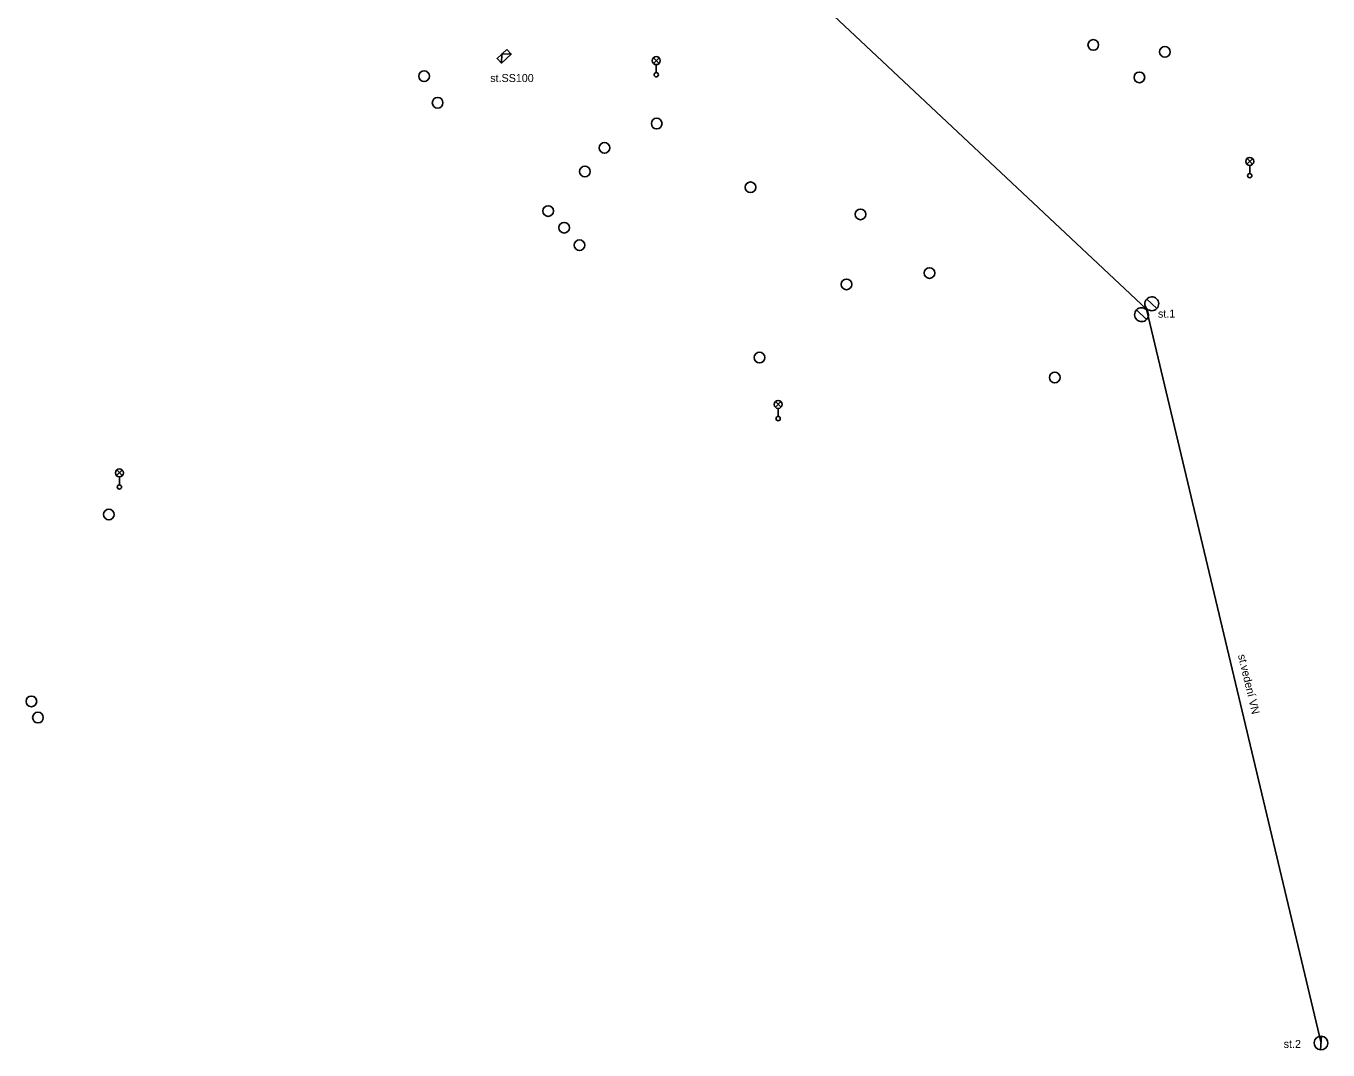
# Model space of a CAD drawing. Extents: x -762500 to -761250, y -1152983 to -1152297.
# Drawn here: x -762376.5 to -762254.5, y -1152983.3 to -1152887.3 of the extents above; entities that cross this region are included whole.
import ezdxf

# ---------------------------------------------------------------- set-up
doc = ezdxf.new("R2010")
doc.units = 0
for name, color, linetype in [('Vrstva 1', 7, 'Continuous'), ('Vrstva 2', 7, 'Continuous'), ('Vrstva 9', 7, 'Continuous')]:
    doc.layers.add(name, color=color, linetype=linetype)

msp = doc.modelspace()

# ---------------------------------------------------------------- linework, layer by layer
at = {"layer": 'Vrstva 1'}
for p, q in [((-762270.557, -1152913.775), (-762271.505, -1152912.885)), ((-762271.515, -1152914.795), (-762272.463, -1152913.905)), ((-762255.117, -1152981.962), (-762255.223, -1152983.258))]:
    msp.add_line(p, q, dxfattribs=at)
for points in [[(-762271.51, -1152913.84), (-762343.79, -1152845.98)], [(-762331.054, -1152889.926), (-762331.92, -1152889.91), (-762331.971, -1152890.775)], [(-762255.17, -1152982.61), (-762271.51, -1152913.84)]]:
    msp.add_lwpolyline(points, dxfattribs=at)
msp.add_lwpolyline([(-762331.461, -1152889.485), (-762332.379, -1152890.335), (-762331.971, -1152890.775), (-762331.054, -1152889.926)], close=True, dxfattribs=at)
for centre, start, end in [((-762271.031, -1152913.33), 136.80274, 316.80274), ((-762271.031, -1152913.33), 316.80274, 136.80274), ((-762271.989, -1152914.35), 136.80274, 316.80274), ((-762271.989, -1152914.35), 316.80274, 136.80274), ((-762255.17, -1152982.61), 85.28506, 265.28506), ((-762255.17, -1152982.61), 265.28506, 85.28506)]:
    msp.add_arc(centre, 0.65, start, end, dxfattribs=at)
at = {"layer": 'Vrstva 9'}
for p, q in [((-762317.724, -1152890.808), (-762317.196, -1152890.28)), ((-762317.188, -1152890.805), (-762317.716, -1152890.276)), ((-762317.46, -1152890.92), (-762317.46, -1152891.67)), ((-762262.114, -1152900.258), (-762261.586, -1152899.73)), ((-762261.578, -1152900.255), (-762262.106, -1152899.726)), ((-762261.85, -1152900.37), (-762261.85, -1152901.12)), ((-762306.304, -1152923.028), (-762305.776, -1152922.5)), ((-762305.768, -1152923.025), (-762306.296, -1152922.496)), ((-762306.04, -1152923.14), (-762306.04, -1152923.89)), ((-762368.034, -1152929.438), (-762367.506, -1152928.91)), ((-762367.498, -1152929.435), (-762368.026, -1152928.906)), ((-762367.77, -1152929.55), (-762367.77, -1152930.3))]:
    msp.add_line(p, q, dxfattribs=at)
for centre, radius in [((-762276.51, -1152889.07), 0.5), ((-762317.46, -1152890.545), 0.375), ((-762269.8, -1152889.72), 0.5), ((-762339.22, -1152892), 0.5), ((-762317.46, -1152891.87), 0.2), ((-762272.19, -1152892.11), 0.5), ((-762337.95, -1152894.49), 0.5), ((-762317.42, -1152896.44), 0.5), ((-762322.31, -1152898.72), 0.5), ((-762261.85, -1152899.995), 0.375), ((-762324.15, -1152900.93), 0.5), ((-762261.85, -1152901.32), 0.2), ((-762308.63, -1152902.41), 0.5), ((-762327.59, -1152904.64), 0.5), ((-762298.33, -1152904.95), 0.5), ((-762326.09, -1152906.2), 0.5), ((-762324.66, -1152907.84), 0.5), ((-762291.86, -1152910.45), 0.5), ((-762299.64, -1152911.51), 0.5), ((-762307.79, -1152918.37), 0.5), ((-762280.12, -1152920.24), 0.5), ((-762306.04, -1152922.765), 0.375), ((-762306.04, -1152924.09), 0.2), ((-762367.77, -1152929.175), 0.375), ((-762367.77, -1152930.5), 0.2), ((-762368.76, -1152933.08), 0.5), ((-762376.02, -1152950.59), 0.5), ((-762375.4, -1152952.11), 0.5)]:
    msp.add_circle(centre, radius, dxfattribs=at)

# ---------------------------------------------------------------- texts
at = {"layer": 'Vrstva 2'}
for s, p in [('st.SS100', (-762333.02, -1152892.55)), ('st.1', (-762270.45, -1152914.63)), ('st.2', (-762258.67, -1152983.07))]:
    msp.add_text(s, height=0.75, dxfattribs=at).set_placement(p)
msp.add_text('st.vedení VN', height=0.75, rotation=283.36584, dxfattribs=at).set_placement((-762262.96, -1152946.27))

doc.saveas('drawing.dxf')
